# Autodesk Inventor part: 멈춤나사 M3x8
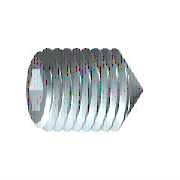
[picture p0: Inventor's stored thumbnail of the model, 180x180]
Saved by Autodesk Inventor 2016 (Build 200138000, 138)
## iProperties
IsCustomPart: 1
Created: 2012-02
Part Number: 멈춤나사 M3x8
Material: 강철, 연강
Description: 6각 소켓 머리 없는 멈춤 나사
Document SubType Name: Modeling
Standard: KS B 1028
Designer: test
Standards Organization: KS
Language: ko-KR
Size Designation: 원추점 M3x8
Categories: <MemberInstance><Categories><Category DisplayName="조임쇠" InternalName="e4da775c-781d-43d5-af7c-5136215cf5a6" Mnemonic="FSTN"><Category DisplayName="볼트" InternalN
Density: 1 g/cm^3
Appearance: 강철
Author: test
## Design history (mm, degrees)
sketch "스케치1"
  geometry: L1 (0, 0)-(5.5, 0); L2 (8, 0.866)-(8, 1.5); L3 (8, 1.5)-(0, 1.5); L4 (8, 0.866)-(6, 0.866); L5 (6, 0.866)-(5.5, 0); L6 (0, -0.3)-(0, 1.8) reference; L7 (0, 1.5)-(0, 0)
  constraints: 13 end point, 3 parallel, 1 collinear, 1 perpendicular, 1 point on line
  dimensions: "d0" = 2 distance of L2.start L4.end (= INTI); "d1" = 60 deg angle of L5 L1; "d2" = 3 diameter of L3 L1 (= NND); "d3" = 1.73205 diameter of L4 L1 (= 1.1547 x SW); "d5" = 8 distance from line of L2 L3.end (= NLG)
revolve "본체" sketch "스케치1" stored, may be unused: angle "d6" = 90 deg
sketch "스케치2"
  geometry: L1 (-0.433, 0.75)-(0.433, 0.75); L2 (0.433, 0.75)-(0.866, 0); L3 (0.866, 0)-(0.433, -0.75); L4 (0.433, -0.75)-(-0.433, -0.75); L5 (-0.433, -0.75)-(-0.866, 0); L6 (-0.866, 0)-(-0.433, 0.75); 3 further points
  constraints: 12 end point, 1 coincident, 1 horizontal, 13 other
extrude "슬롯" join sketch "스케치2" taper "d7" = 0 deg; stored distance "d21" = 10
workaxis "Work Axis1"
workplane "Work Plane1"
sketch "스케치4"
  geometry: L1 (0, 0.15)-(-1.35, 1.5) reference; L2 (0, -0.15)-(-1.35, -1.5) reference; L3 (-1.35, -1.5)-(0.15, 0); L4 (-1.35, 1.5)-(0.15, 0); 2 further points
  constraints: 4 end point, 1 coincident, 1 collinear, 1 horizontal alignment
body "Solid1"
feature "스레드" dims "d12" = 8 (= NLG), "d13" = 0
chamfer "모따기1" distance "d8" = 1.35 (computed from NND, SPD, FAWI); stored, may be unused: angle "d9" = 45 deg (= FAWI), second distance "d34" = 1.35 (computed from NND, SPD, FAWI)
chamfer "모따기2" distance "d10" = 0.30673 (= -0.5 x GD1 + 0.5 x NND); stored, may be unused: angle "d11" = 45 deg (= FAWI), second distance "d35" = 0.30673 (= -0.5 x GD1 + 0.5 x NND)
other parameters: "NND" = 3 [user parameter; used in 5 equation terms], "NLG" = 8 [user parameter; used in 2 equation terms], "INTI" = 2 [user parameter; used in 1 equation term], "FAWI" = 45 deg [user parameter; used in 4 equation terms], "SW" = 1.5 [user parameter; used in 2 equation terms], "GD1" = 2.38655 (= THREADDIA - 1.2269 x PTC) [user parameter; used in 2 equation terms], "d4" = 0, "FAWI1" = 45 deg [user parameter], "SPD" = 0.3 [user parameter; used in 2 equation terms], "d36" = 0, "d37" = 0, "GUL" = 0.30673 (= 0.61345 x PTC) [user parameter], "TOA" = 30 deg [user parameter], "THREADDIA" = 3 [user parameter; used in 1 equation term], "PTC" = 0.5 [user parameter; used in 4 equation terms], "GAL" = 0.30673 (= 0.61345 x PTC) [user parameter], "E0" = 1.7325 (= 1.155 x SW) [user parameter]
